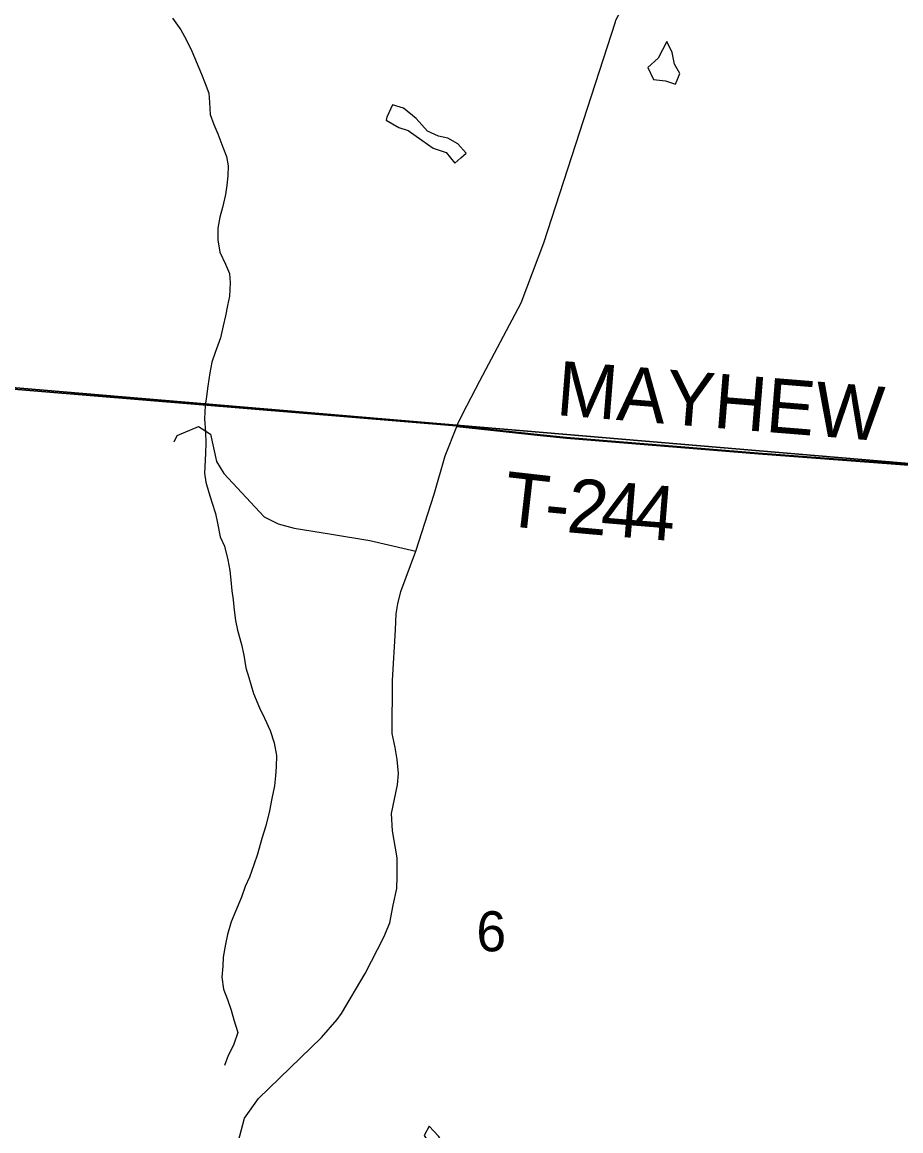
# Model space of a CAD drawing. Extents: x 0 to 42, y 0 to 22.
# Drawn here: x 2.271 to 2.73, y 19.416 to 19.995 of the extents above; entities that cross this region are included whole.
import ezdxf

# ---------------------------------------------------------------- set-up
doc = ezdxf.new("R2010")
doc.units = 0
for name, color, linetype in [('GM_X_County_Road', 7, 'Continuous'), ('GM_X_Minor_Lake', 7, 'Continuous'), ('GM_X_Minor_River', 7, 'Continuous'), ('GM_X_Section', 7, 'Continuous'), ('GM_X_Section_Text', 7, 'Continuous'), ('GM_X_Township_Road', 7, 'Continuous'), ('GM_X_Township_Road_Text', 7, 'Continuous')]:
    doc.layers.add(name, color=color, linetype=linetype)

msp = doc.modelspace()

# ---------------------------------------------------------------- linework, layer by layer
at = {"layer": 'GM_X_County_Road'}
msp.add_line((2.49771, 19.78358), (2.49833, 19.78497), dxfattribs=at)
for points in [[(2.49833, 19.78497), (2.50062, 19.79005), (2.50971, 19.80748), (2.53135, 19.84827), (2.54322, 19.8796), (2.58053, 19.99503), (2.5808, 19.99588), (2.58508, 20.00417), (2.59331, 20.02036)], [(2.47636, 19.71839), (2.48583, 19.74823), (2.49167, 19.76822), (2.49771, 19.78358)], [(2.38096, 19.4004), (2.38681, 19.42215), (2.39416, 19.43237), (2.42706, 19.46432), (2.4352, 19.47367), (2.43744, 19.47687), (2.4499, 19.49779), (2.45956, 19.51676), (2.46275, 19.52419), (2.46451, 19.53338), (2.46635, 19.54217), (2.46651, 19.54818), (2.46651, 19.55813), (2.4641, 19.5723), (2.46367, 19.58133), (2.46673, 19.59642), (2.46717, 19.60222), (2.46662, 19.60955), (2.46553, 19.6159), (2.46395, 19.6231), (2.4641, 19.65077), (2.46567, 19.67732), (2.46603, 19.68563), (2.46691, 19.69094), (2.46844, 19.6973), (2.47636, 19.71839)]]:
    msp.add_lwpolyline(points, dxfattribs=at)
at = {"layer": 'GM_X_Minor_Lake'}
for points in [[(2.6075, 19.98474), (2.60295, 19.97603), (2.59746, 19.97111), (2.60048, 19.96485), (2.60672, 19.96427), (2.61201, 19.96237), (2.61321, 19.96536)], [(2.61321, 19.96536), (2.61429, 19.96805), (2.61146, 19.97298), (2.61014, 19.97905), (2.6075, 19.98474)], [(2.49977, 19.9239), (2.50263, 19.92648), (2.49828, 19.93122), (2.49299, 19.93426), (2.48807, 19.93522), (2.4824, 19.93788), (2.47654, 19.94452), (2.46993, 19.94984), (2.46407, 19.95174), (2.46122, 19.9453)], [(2.46122, 19.9453), (2.46084, 19.94359), (2.46746, 19.93979), (2.47237, 19.93827), (2.47937, 19.93314), (2.48541, 19.92896), (2.49222, 19.92668), (2.49675, 19.92117), (2.49977, 19.9239)], [(2.48878, 19.4119), (2.48814, 19.41269), (2.48323, 19.418), (2.48058, 19.41308), (2.48454, 19.40719), (2.48435, 19.40075), (2.48888, 19.39486), (2.4866, 19.38861), (2.48792, 19.38349), (2.49454, 19.38519)]]:
    msp.add_lwpolyline(points, dxfattribs=at)
at = {"layer": 'GM_X_Minor_River'}
msp.add_lwpolyline([(2.34925, 19.99697), (2.35356, 19.99088), (2.35636, 19.98574), (2.35935, 19.97965), (2.36437, 19.96767), (2.36623, 19.96273), (2.36809, 19.95779), (2.36843, 19.95285), (2.36877, 19.94659), (2.37082, 19.94146), (2.37286, 19.93652), (2.37546, 19.92948), (2.37732, 19.92473), (2.37824, 19.91979), (2.37801, 19.91449), (2.3776, 19.90975), (2.37681, 19.90482), (2.37525, 19.89801), (2.37389, 19.8929), (2.37291, 19.88721), (2.37286, 19.88115), (2.37396, 19.87469), (2.37694, 19.86842), (2.37899, 19.86347), (2.37933, 19.85873), (2.37891, 19.85171), (2.37793, 19.84679), (2.37695, 19.84149), (2.37559, 19.83619), (2.37422, 19.82994), (2.37152, 19.82218), (2.36978, 19.81726), (2.36861, 19.81158), (2.36761, 19.80457), (2.36701, 19.79927), (2.36622, 19.79453), (2.36598, 19.78752), (2.3665, 19.78069), (2.36665, 19.775), (2.36643, 19.7695), (2.36598, 19.75926), (2.36651, 19.75452), (2.36818, 19.74901), (2.36966, 19.74407), (2.3717, 19.73818), (2.37261, 19.73305), (2.37408, 19.72584), (2.37631, 19.72108), (2.37816, 19.71386), (2.37907, 19.70836), (2.3796, 19.70323), (2.38013, 19.69773), (2.38085, 19.69299), (2.38138, 19.68767), (2.3821, 19.68217), (2.38321, 19.67723), (2.38523, 19.66963), (2.38652, 19.66412), (2.38742, 19.65748), (2.38909, 19.65235), (2.39149, 19.64399), (2.39466, 19.63657), (2.39727, 19.63125), (2.40025, 19.62478), (2.40229, 19.61832), (2.40357, 19.61167), (2.40334, 19.6058), (2.40293, 19.60106), (2.40252, 19.59575), (2.40115, 19.58912), (2.39978, 19.58269), (2.39802, 19.57492), (2.3959, 19.5683), (2.39357, 19.56016), (2.39164, 19.55449), (2.38932, 19.54805), (2.38721, 19.54314), (2.38528, 19.53765), (2.38201, 19.53009), (2.3799, 19.52479), (2.37796, 19.51817), (2.37679, 19.51306), (2.37561, 19.50624), (2.37539, 19.5015), (2.37497, 19.49581), (2.37587, 19.48955), (2.37792, 19.48423), (2.37977, 19.47852), (2.38125, 19.47358), (2.38329, 19.46693), (2.38097, 19.46031), (2.37828, 19.45483), (2.37636, 19.44972)], dxfattribs=at)
at = {"layer": 'GM_X_Section'}
for points in [[(2.29013, 20.3056), (2.8507, 20.2571), (2.81539, 19.7575), (2.79152, 19.75944), (2.25084, 19.80525)], [(2.79152, 19.75944), (2.74672, 19.25266), (2.20829, 19.28863), (2.21316, 19.35245), (2.25084, 19.80525)]]:
    msp.add_lwpolyline(points, close=True, dxfattribs=at)
at = {"layer": 'GM_X_Township_Road'}
for points in [[(3.46538, 19.71037), (3.44159, 19.71277), (3.33698, 19.72171), (3.29207, 19.72394), (3.1748, 19.72954), (3.10373, 19.73376), (3.06033, 19.73769), (2.97375, 19.74379), (2.95634, 19.74517), (2.95029, 19.74585), (2.90017, 19.75092), (2.84643, 19.75618), (2.81727, 19.75726), (2.7615, 19.76157), (2.6552, 19.76956), (2.55498, 19.77777), (2.54121, 19.77915), (2.4976, 19.78384), (2.25126, 19.80438)], [(2.25126, 19.80438), (2.4976, 19.78384), (2.54121, 19.77915), (2.55498, 19.77777), (2.6552, 19.76956), (2.7615, 19.76157), (2.81727, 19.75726), (2.84643, 19.75618), (2.90017, 19.75092), (2.95029, 19.74585), (2.95634, 19.74517), (2.97375, 19.74379), (3.06033, 19.73769), (3.10373, 19.73376), (3.1748, 19.72954), (3.29207, 19.72394), (3.33698, 19.72171), (3.44159, 19.71277), (3.46538, 19.71037)], [(2.35006, 19.77563), (2.35163, 19.7788), (2.36269, 19.78351), (2.36901, 19.77953), (2.37213, 19.76535), (2.37607, 19.759), (2.39705, 19.73639), (2.40431, 19.73267), (2.41279, 19.73037), (2.43225, 19.72737), (2.45223, 19.72401), (2.47186, 19.71941), (2.47636, 19.71839)], [(2.47636, 19.71839), (2.48583, 19.74823), (2.49167, 19.76822), (2.49771, 19.78358)], [(2.49771, 19.78358), (2.54132, 19.77889), (2.55508, 19.77751), (2.65531, 19.7693), (2.76161, 19.76131), (2.81738, 19.757)]]:
    msp.add_lwpolyline(points, dxfattribs=at)

# ---------------------------------------------------------------- texts
at = {"layer": 'GM_X_Section_Text'}
msp.add_text('6', height=0.02093, rotation=0.00001, dxfattribs=at).set_placement((2.50794, 19.50934))
at = {"layer": 'GM_X_Township_Road_Text'}
for s, height, rotation, p in [('MAYHEW', 0.028409, 355.39656, (2.54914, 19.78961)), ('T', 0.02841, 353.52777, (2.52116, 19.732)), ('2', 0.02841, 354.88822, (2.55462, 19.72841)), ('4', 0.02841, 355.26978, (2.57226, 19.72683)), ('4', 0.02841, 355.36905, (2.58975, 19.72538)), ('-', 0.02841, 354.46502, (2.54278, 19.72955))]:
    msp.add_text(s, height=height, rotation=rotation, dxfattribs=at).set_placement(p)

doc.saveas('drawing.dxf')
